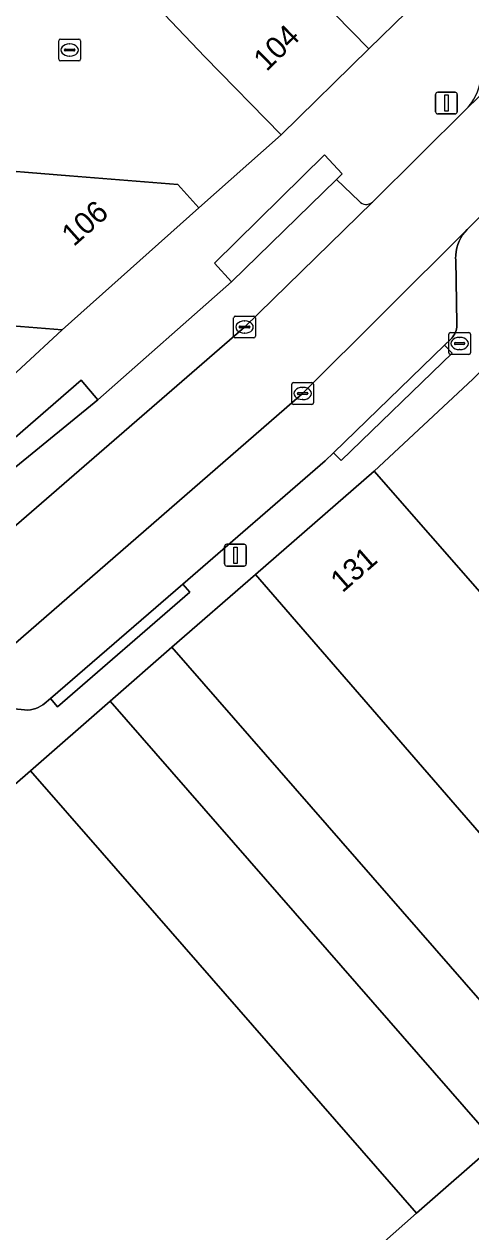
# Model space of a CAD drawing. Extents: x 160856 to 161310, y 384024 to 384878.
# Drawn here: x 161025.6 to 161046.1, y 384589.8 to 384645.2 of the extents above; entities that cross this region are included whole.
import ezdxf

# ---------------------------------------------------------------- set-up
doc = ezdxf.new("R2010")
doc.units = 0
for name, color, linetype in [('IMGEO_Brandkraan', 7, 'Continuous'), ('IMGEO_Erf', 7, 'Continuous'), ('IMGEO_Kolk', 7, 'Continuous'), ('IMGEO_Lichtmast', 7, 'Continuous'), ('IMGEO_Pand', 7, 'Continuous'), ('IMGEO_Pand_nummerreeks', 7, 'Continuous'), ('IMGEO_Parkeervlak_open', 7, 'Continuous'), ('IMGEO_Rijbaan_lokaal_gesloten', 7, 'Continuous'), ('IMGEO_Rijbaan_lokaal_open', 7, 'Continuous'), ('IMGEO_Voetpad_open', 7, 'Continuous')]:
    doc.layers.add(name, color=color, linetype=linetype)

msp = doc.modelspace()

# ---------------------------------------------------------------- linework, layer by layer
at = {"layer": 'IMGEO_Brandkraan'}
for p, q in [((161045.126, 384630.156), (161045.126, 384631.008)), ((161045.201, 384631.082), (161046.053, 384631.082)), ((161046.127, 384631.008), (161046.127, 384630.156)), ((161045.385, 384630.576), (161045.385, 384630.588)), ((161045.823, 384630.539), (161045.425, 384630.539)), ((161045.428, 384630.625), (161045.826, 384630.625)), ((161045.614, 384630.862), (161045.639, 384630.862)), ((161045.869, 384630.588), (161045.869, 384630.576)), ((161046.053, 384630.082), (161045.201, 384630.082)), ((161045.637, 384630.302), (161045.612, 384630.302))]:
    msp.add_line(p, q, dxfattribs=at)
for points in [[(161045.126, 384630.156), (161045.126, 384631.008)], [(161045.201, 384631.082), (161046.053, 384631.082)], [(161046.127, 384631.008), (161046.127, 384630.156)], [(161046.053, 384630.082), (161045.201, 384630.082)]]:
    msp.add_lwpolyline(points, dxfattribs=at)
for centre, radius, start, end in [((161045.203, 384631.006), 0.0765, 91.552, 178.448), ((161045.203, 384631.006), 0.0765, 91.552, 178.448), ((161046.051, 384631.006), 0.0765, 1.552, 88.448), ((161046.051, 384631.006), 0.0765, 1.552, 88.448), ((161045.425, 384630.585), 0.0403, 85.8775, 175.7526), ((161045.422, 384630.575), 0.0366, 178.938, 274.7102), ((161045.826, 384630.582), 0.043, 264.8664, 352.4533), ((161045.83, 384630.587), 0.0386, 1.7309, 96.639), ((161045.203, 384630.158), 0.0765, 181.552, 268.448), ((161045.203, 384630.158), 0.0765, 181.552, 268.448), ((161046.051, 384630.158), 0.0765, 271.552, 358.448), ((161046.051, 384630.158), 0.0765, 271.552, 358.448)]:
    msp.add_arc(centre, radius, start, end, dxfattribs=at)
for centre, major_axis, ratio, start_param, end_param in [((161045.613, 384630.582), (-0.387, 0.002), 0.722429, 4.712389, 7.853982), ((161045.638, 384630.582), (-0.39, 0.002), 0.717154, 1.570796, 4.712389)]:
    msp.add_ellipse(centre, major_axis=major_axis, ratio=ratio, start_param=start_param, end_param=end_param, dxfattribs=at)
at = {"layer": 'IMGEO_Erf'}
msp.add_lwpolyline([(160982.658, 384634.928), (160978.666, 384634.124), (160981.076, 384634.38), (160981.729, 384632.693), (160983.224, 384628.829), (160983.529, 384628.84), (160998.052, 384629.357), (161000, 384624.44), (161002.264, 384618.717), (161016.56, 384624.082), (161017.955, 384622.48), (161027.384, 384631.214), (161022.401, 384631.613), (161009.148, 384632.67), (160988.131, 384634.654), (160982.633, 384635.174)], close=True, dxfattribs=at)
msp.add_lwpolyline([(161046.227, 384628.945), (161041.697, 384624.725), (161051.945, 384613.029)], dxfattribs=at)
at = {"layer": 'IMGEO_Kolk'}
for p, q in [((161027.23, 384643.633), (161027.23, 384644.485)), ((161027.305, 384644.559), (161028.157, 384644.559)), ((161027.718, 384644.339), (161027.743, 384644.339)), ((161028.231, 384644.485), (161028.231, 384643.633)), ((161027.489, 384644.053), (161027.489, 384644.065)), ((161027.927, 384644.016), (161027.529, 384644.016)), ((161027.532, 384644.102), (161027.93, 384644.102)), ((161027.741, 384643.779), (161027.716, 384643.779)), ((161027.973, 384644.065), (161027.973, 384644.053)), ((161028.157, 384643.559), (161027.305, 384643.559)), ((161035.256, 384630.912), (161035.256, 384631.764)), ((161035.331, 384631.838), (161036.183, 384631.838)), ((161035.744, 384631.618), (161035.769, 384631.618)), ((161036.257, 384631.764), (161036.257, 384630.912)), ((161035.515, 384631.332), (161035.515, 384631.344)), ((161035.953, 384631.295), (161035.555, 384631.295)), ((161035.558, 384631.381), (161035.956, 384631.381)), ((161035.767, 384631.058), (161035.742, 384631.058)), ((161035.999, 384631.344), (161035.999, 384631.332)), ((161036.183, 384630.838), (161035.331, 384630.838)), ((161037.92, 384627.862), (161037.92, 384628.714)), ((161037.995, 384628.788), (161038.847, 384628.788)), ((161038.921, 384628.714), (161038.921, 384627.862)), ((161038.179, 384628.282), (161038.179, 384628.294)), ((161038.617, 384628.245), (161038.219, 384628.245)), ((161038.222, 384628.331), (161038.62, 384628.331)), ((161038.408, 384628.568), (161038.433, 384628.568)), ((161038.663, 384628.294), (161038.663, 384628.282)), ((161038.847, 384627.788), (161037.995, 384627.788)), ((161038.431, 384628.008), (161038.406, 384628.008))]:
    msp.add_line(p, q, dxfattribs=at)
for points in [[(161027.23, 384643.633), (161027.23, 384644.485)], [(161027.305, 384644.559), (161028.157, 384644.559)], [(161028.231, 384644.485), (161028.231, 384643.633)], [(161028.157, 384643.559), (161027.305, 384643.559)], [(161035.256, 384630.912), (161035.256, 384631.764)], [(161035.331, 384631.838), (161036.183, 384631.838)], [(161036.257, 384631.764), (161036.257, 384630.912)], [(161036.183, 384630.838), (161035.331, 384630.838)], [(161037.92, 384627.862), (161037.92, 384628.714)], [(161037.995, 384628.788), (161038.847, 384628.788)], [(161038.921, 384628.714), (161038.921, 384627.862)], [(161038.847, 384627.788), (161037.995, 384627.788)]]:
    msp.add_lwpolyline(points, dxfattribs=at)
for centre, radius, start, end in [((161027.307, 384644.483), 0.0765, 91.552, 178.448), ((161027.307, 384644.483), 0.0765, 91.552, 178.448), ((161028.155, 384644.483), 0.0765, 1.552, 88.448), ((161028.155, 384644.483), 0.0765, 1.552, 88.448), ((161027.529, 384644.062), 0.0403, 85.8775, 175.7526), ((161027.526, 384644.052), 0.0366, 178.938, 274.7102), ((161027.93, 384644.059), 0.043, 264.8664, 352.4533), ((161027.934, 384644.064), 0.0386, 1.7309, 96.639), ((161027.307, 384643.635), 0.0765, 181.552, 268.448), ((161027.307, 384643.635), 0.0765, 181.552, 268.448), ((161028.155, 384643.635), 0.0765, 271.552, 358.448), ((161028.155, 384643.635), 0.0765, 271.552, 358.448), ((161035.333, 384631.762), 0.0765, 91.552, 178.448), ((161035.333, 384631.762), 0.0765, 91.552, 178.448), ((161036.181, 384631.762), 0.0765, 1.552, 88.448), ((161036.181, 384631.762), 0.0765, 1.552, 88.448), ((161035.555, 384631.341), 0.0403, 85.8775, 175.7526), ((161035.552, 384631.331), 0.0366, 178.938, 274.7102), ((161035.956, 384631.338), 0.043, 264.8664, 352.4533), ((161035.96, 384631.343), 0.0386, 1.7309, 96.639), ((161035.333, 384630.914), 0.0765, 181.552, 268.448), ((161035.333, 384630.914), 0.0765, 181.552, 268.448), ((161036.181, 384630.914), 0.0765, 271.552, 358.448), ((161036.181, 384630.914), 0.0765, 271.552, 358.448), ((161037.997, 384628.712), 0.0765, 91.552, 178.448), ((161037.997, 384628.712), 0.0765, 91.552, 178.448), ((161038.845, 384628.712), 0.0765, 1.552, 88.448), ((161038.845, 384628.712), 0.0765, 1.552, 88.448), ((161038.219, 384628.291), 0.0403, 85.8775, 175.7526), ((161038.216, 384628.281), 0.0366, 178.938, 274.7102), ((161038.62, 384628.288), 0.043, 264.8664, 352.4533), ((161038.624, 384628.293), 0.0386, 1.7309, 96.639), ((161037.997, 384627.864), 0.0765, 181.552, 268.448), ((161037.997, 384627.864), 0.0765, 181.552, 268.448), ((161038.845, 384627.864), 0.0765, 271.552, 358.448), ((161038.845, 384627.864), 0.0765, 271.552, 358.448)]:
    msp.add_arc(centre, radius, start, end, dxfattribs=at)
for centre, major_axis, ratio, start_param, end_param in [((161027.717, 384644.059), (-0.387, 0.002), 0.722429, 4.712389, 7.853982), ((161027.742, 384644.059), (-0.39, 0.002), 0.717154, 1.570796, 4.712389), ((161035.743, 384631.338), (-0.387, 0.002), 0.722429, 4.712389, 7.853982), ((161035.768, 384631.338), (-0.39, 0.002), 0.717154, 1.570796, 4.712389), ((161038.407, 384628.288), (-0.387, 0.002), 0.722429, 4.712389, 7.853982), ((161038.432, 384628.288), (-0.39, 0.002), 0.717154, 1.570796, 4.712389)]:
    msp.add_ellipse(centre, major_axis=major_axis, ratio=ratio, start_param=start_param, end_param=end_param, dxfattribs=at)
at = {"layer": 'IMGEO_Lichtmast'}
for p, q in [((161044.526, 384641.224), (161044.526, 384642.024)), ((161044.526, 384642.024), (161044.526, 384641.224)), ((161044.626, 384642.124), (161045.416, 384642.124)), ((161045.416, 384642.124), (161044.626, 384642.124)), ((161045.516, 384642.024), (161045.516, 384641.224)), ((161045.516, 384641.224), (161045.516, 384642.024)), ((161045.416, 384641.124), (161044.626, 384641.124)), ((161044.626, 384641.124), (161045.416, 384641.124)), ((161034.842, 384620.46), (161034.842, 384621.26)), ((161034.842, 384621.26), (161034.842, 384620.46)), ((161034.942, 384621.36), (161035.732, 384621.36)), ((161035.732, 384621.36), (161034.942, 384621.36)), ((161035.832, 384621.26), (161035.832, 384620.46)), ((161035.832, 384620.46), (161035.832, 384621.26)), ((161035.732, 384620.36), (161034.942, 384620.36)), ((161034.942, 384620.36), (161035.732, 384620.36))]:
    msp.add_line(p, q, dxfattribs=at)
for points in [[(161044.946, 384641.999), (161045.096, 384641.999), (161045.096, 384641.249), (161044.946, 384641.249), (161044.946, 384641.999)], [(161035.262, 384621.235), (161035.412, 384621.235), (161035.412, 384620.485), (161035.262, 384620.485), (161035.262, 384621.235)]]:
    msp.add_lwpolyline(points, dxfattribs=at)
for centre, start, end in [((161044.626, 384642.024), 90, 180), ((161044.626, 384642.024), 90, 180), ((161045.416, 384642.024), 0, 90), ((161045.416, 384642.024), 360, 90), ((161044.626, 384641.224), 180, 270), ((161044.626, 384641.224), 180, 270), ((161045.416, 384641.224), 270, 0), ((161045.416, 384641.224), 270, 0), ((161034.942, 384621.26), 90, 180), ((161034.942, 384621.26), 90, 180), ((161035.732, 384621.26), 0, 90), ((161035.732, 384621.26), 360, 90), ((161034.942, 384620.46), 180, 270), ((161034.942, 384620.46), 180, 270), ((161035.732, 384620.46), 270, 0), ((161035.732, 384620.46), 270, 0)]:
    msp.add_arc(centre, 0.1, start, end, dxfattribs=at)
at = {"layer": 'IMGEO_Pand'}
for points in [[(161036.163, 384657.446), (161035.583, 384656.879), (161034.191, 384655.517), (161032.2, 384653.569), (161032.68, 384653.079), (161032.814, 384652.942), (161041.458, 384644.107), (161043.184, 384645.796), (161043.192, 384646.544), (161045.05, 384648.363)], [(161032.68, 384653.079), (161028.69, 384649.268), (161033.936, 384643.741), (161037.434, 384640.168), (161041.458, 384644.107), (161032.814, 384652.942)], [(161023.199, 384638.753), (161009.711, 384639.726), (160988.813, 384641.433), (160988.131, 384634.654), (161009.148, 384632.67), (161022.401, 384631.613), (161027.384, 384631.214), (161033.664, 384636.809), (161032.7, 384637.891), (161027.716, 384638.289), (161023.191, 384638.65)], [(161065.299, 384606.33), (161066.069, 384607.092), (161059.889, 384613.353), (161056.376, 384616.911), (161051.945, 384613.029), (161041.697, 384624.725), (161036.251, 384619.971), (161039.526, 384616.193), (161053.907, 384599.6), (161054.646, 384598.766), (161064.12, 384606.995)], [(161030.393, 384578.898), (161043.64, 384590.649), (161029.215, 384607.194), (161025.93, 384610.963), (161012.864, 384599.573), (161020.168, 384590.958)], [(161101.019, 384586.171), (161065.299, 384606.33), (161064.12, 384606.995), (161054.646, 384598.766), (161053.907, 384599.6), (161050.139, 384596.315), (161047.302, 384593.842), (161043.64, 384590.649), (161030.393, 384578.898), (161033.987, 384574.979), (161024.428, 384568.037), (161050.778, 384531.991), (161074.251, 384547.573), (161066.613, 384557.83), (161061.858, 384564.216), (161074.987, 384573.785), (161078.354, 384576.239), (161086.977, 384571.374), (161090.784, 384569.226), (161091.331, 384568.917)]]:
    msp.add_lwpolyline(points, close=True, dxfattribs=at)
at = {"layer": 'IMGEO_Parkeervlak_open'}
for points in [[(161045.943, 384641.353), (161047.62, 384642.996), (161093.847, 384688.359), (161094.179, 384688.665), (161098.356, 384692.696)], [(161041.01, 384637.114), (161039.982, 384638.114), (161035.157, 384633.415), (161029.017, 384627.993), (161023.823, 384623.759), (161024.666, 384622.796)], [(161021.935, 384619.355), (161035.757, 384631.338), (161041.622, 384637.072)], [(161025.029, 384613.826), (161025.803, 384613.747), (161025.927, 384613.761), (161026.05, 384613.785), (161026.17, 384613.821), (161026.287, 384613.867), (161026.398, 384613.923), (161026.505, 384613.989), (161026.559, 384614.028), (161026.847, 384614.277), (161032.916, 384619.532), (161039.454, 384625.193), (161039.836, 384625.563), (161044.935, 384630.503), (161045.213, 384630.773), (161045.27, 384630.83), (161045.322, 384630.892), (161045.367, 384630.959), (161045.407, 384631.029), (161045.441, 384631.102), (161045.467, 384631.178), (161045.487, 384631.257), (161045.5, 384631.336), (161045.505, 384631.417), (161045.504, 384631.485), (161045.446, 384634.435), (161045.444, 384634.479), (161045.447, 384634.644), (161045.464, 384634.808), (161045.496, 384634.969), (161045.542, 384635.128), (161045.602, 384635.281), (161045.675, 384635.428), (161045.762, 384635.568), (161045.86, 384635.7), (161045.97, 384635.823), (161038.406, 384628.276), (161000, 384594.865)]]:
    msp.add_lwpolyline(points, dxfattribs=at)
for points in [[(161039.526, 384616.193), (161036.251, 384619.971), (161032.425, 384616.632), (161050.139, 384596.315), (161053.907, 384599.6)], [(161029.59, 384614.158), (161025.93, 384610.963), (161029.215, 384607.194), (161043.64, 384590.649), (161047.302, 384593.842)]]:
    msp.add_lwpolyline(points, close=True, dxfattribs=at)
for centre, radius, start, end in [((161044.273, 384642.969), 2.324, 315.9544, 353.1621), ((161041.338, 384637.412), 0.443, 222.2874, 309.8608)]:
    msp.add_arc(centre, radius, start, end, dxfattribs=at)
at = {"layer": 'IMGEO_Rijbaan_lokaal_gesloten'}
for points in [[(161045.97, 384635.823), (161048.906, 384638.739), (161096.984, 384685.767), (161094.179, 384688.665), (161093.847, 384688.359), (161047.62, 384642.996), (161045.943, 384641.353), (161041.622, 384637.072), (161035.757, 384631.338), (161021.935, 384619.355), (161000, 384600.273), (160978.384, 384581.429), (160977.321, 384580.465), (160976.957, 384580.135), (160976.745, 384579.943)], [(160980.308, 384577.714), (161000, 384594.865), (161038.406, 384628.276), (161045.97, 384635.823)]]:
    msp.add_lwpolyline(points, dxfattribs=at)
at = {"layer": 'IMGEO_Rijbaan_lokaal_open'}
for points in [[(161024.93, 384653.23), (161023.003, 384655.261), (161022.327, 384655.974), (161021.518, 384655.255), (161019.495, 384656.588), (161017.397, 384654.724), (161014.337, 384654.905), (161012.121, 384657.087), (161011.607, 384650.352), (161011.266, 384646.094), (161023.706, 384645.1), (161023.199, 384638.753), (161023.191, 384638.65), (161027.716, 384638.289), (161032.7, 384637.891), (161033.664, 384636.809), (161037.434, 384640.168), (161033.936, 384643.741), (161028.69, 384649.268)], [(161032.425, 384616.632), (161029.59, 384614.158), (161047.302, 384593.842), (161050.139, 384596.315)]]:
    msp.add_lwpolyline(points, close=True, dxfattribs=at)
at = {"layer": 'IMGEO_Voetpad_open'}
for points in [[(161043.184, 384645.796), (161041.458, 384644.107), (161037.434, 384640.168), (161033.664, 384636.809), (161027.384, 384631.214), (161017.955, 384622.48), (161000, 384606.866), (160994.768, 384602.349), (160990.689, 384598.828), (160973.995, 384584.418), (160977.218, 384580.587)], [(161041.622, 384637.072), (161045.943, 384641.353)], [(161024.666, 384622.796), (161023.823, 384623.759), (161023.116, 384624.443), (161028.261, 384628.901), (161029.017, 384627.993), (161035.157, 384633.415), (161034.38, 384634.274), (161039.431, 384639.242), (161040.232, 384638.368), (161039.982, 384638.114), (161041.01, 384637.114)], [(161048.906, 384638.739), (161045.97, 384635.823), (161045.86, 384635.7), (161045.762, 384635.568), (161045.675, 384635.428), (161045.602, 384635.281), (161045.542, 384635.128), (161045.496, 384634.969), (161045.464, 384634.808), (161045.447, 384634.644), (161045.444, 384634.479), (161045.446, 384634.435), (161045.504, 384631.485), (161045.505, 384631.417), (161045.5, 384631.336), (161045.487, 384631.257), (161045.467, 384631.178), (161045.441, 384631.102), (161045.407, 384631.029), (161045.367, 384630.959), (161045.322, 384630.892), (161045.27, 384630.83), (161045.213, 384630.773), (161044.935, 384630.503), (161045.282, 384630.144), (161040.183, 384625.204), (161039.836, 384625.563), (161039.454, 384625.193), (161032.916, 384619.532), (161033.243, 384619.155), (161027.174, 384613.9), (161026.847, 384614.277), (161026.559, 384614.028), (161026.505, 384613.989), (161026.398, 384613.923), (161026.287, 384613.867), (161026.17, 384613.821), (161026.05, 384613.785), (161025.927, 384613.761), (161025.803, 384613.747), (161025.029, 384613.826)], [(161012.864, 384599.573), (161025.93, 384610.963), (161029.59, 384614.158), (161032.425, 384616.632), (161036.251, 384619.971), (161041.697, 384624.725), (161046.227, 384628.945), (161049.957, 384632.607), (161050.184, 384632.83), (161050.57, 384632.437), (161052.048, 384633.889), (161052.055, 384634.72), (161053.013, 384635.66), (161053.692, 384635.654), (161053.986, 384635.97), (161054.714, 384636.676)]]:
    msp.add_lwpolyline(points, dxfattribs=at)
for points in [[(161035.157, 384633.415), (161039.982, 384638.114), (161040.232, 384638.368), (161039.431, 384639.242), (161034.38, 384634.274)], [(161044.935, 384630.503), (161039.836, 384625.563), (161040.183, 384625.204), (161045.282, 384630.144)], [(161023.823, 384623.759), (161029.017, 384627.993), (161028.261, 384628.901), (161023.116, 384624.443)], [(161032.916, 384619.532), (161026.847, 384614.277), (161027.174, 384613.9), (161033.243, 384619.155)]]:
    msp.add_lwpolyline(points, close=True, dxfattribs=at)
for centre, radius, start, end in [((161044.273, 384642.969), 2.324, 315.9544, 353.1621), ((161041.338, 384637.412), 0.443, 222.2874, 309.8608)]:
    msp.add_arc(centre, radius, start, end, dxfattribs=at)

# ---------------------------------------------------------------- texts
at = {"layer": 'IMGEO_Pand_nummerreeks'}
for s, rotation, p in [('104', 44.387, (161036.764, 384643.038)), ('106', 41.6532, (161027.914, 384635.003)), ('131', 41.1188, (161040.247, 384619.105))]:
    msp.add_text(s, height=1, rotation=rotation, dxfattribs=at).set_placement(p)

doc.saveas('drawing.dxf')
